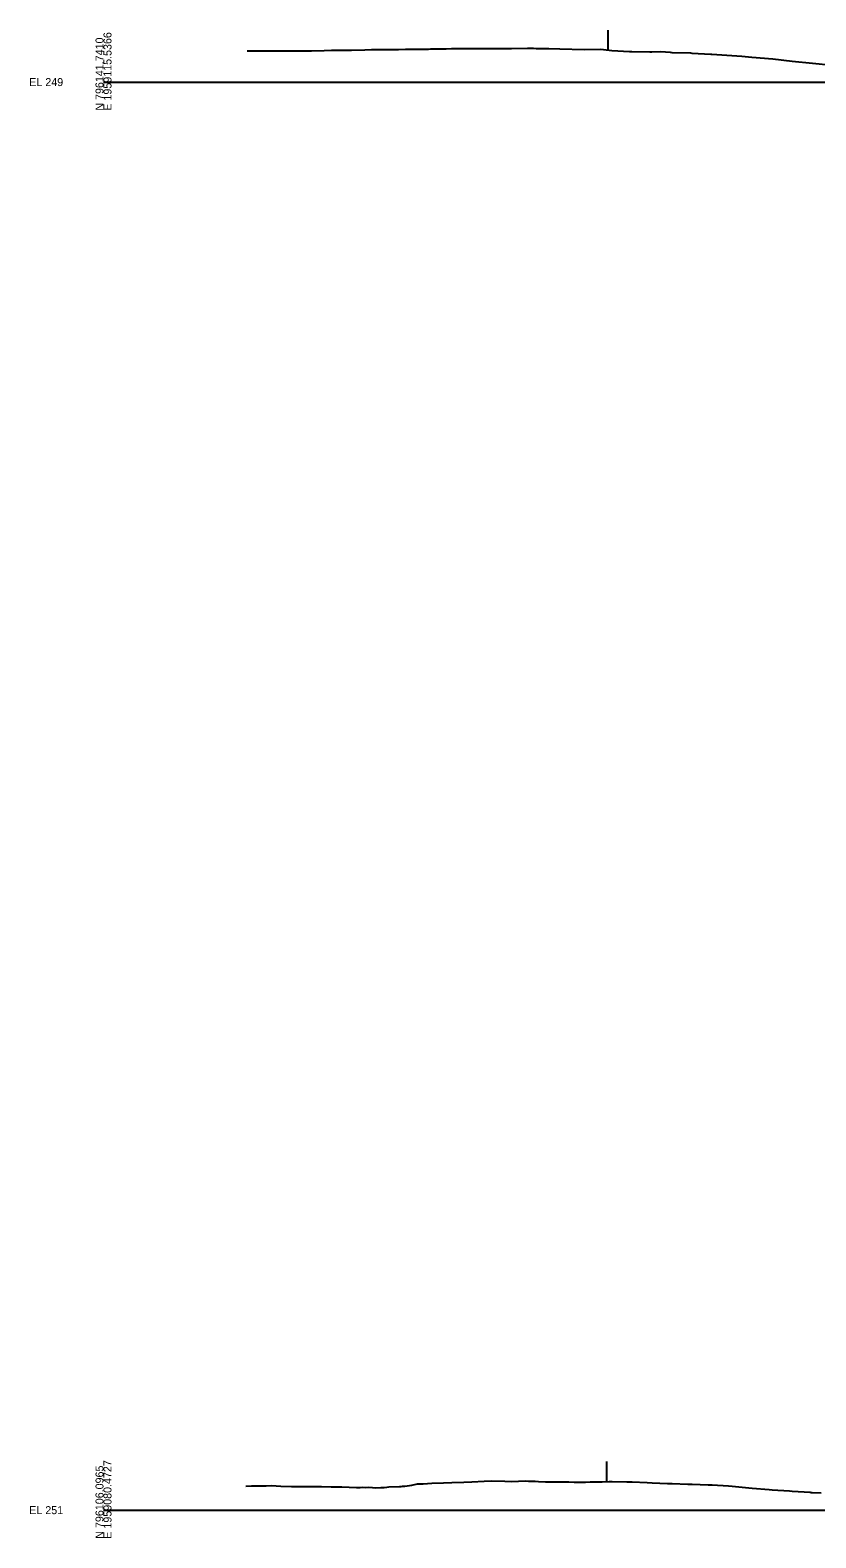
# Model space of a CAD drawing. Extents: x -4026 to 9638, y -10 to 19609.
# Drawn here: x -2026 to -1750, y 16490 to 17018 of the extents above; entities that cross this region are included whole.
import ezdxf

# ---------------------------------------------------------------- set-up
doc = ezdxf.new("R2010")
doc.units = 0
for name, color, linetype in [('Default', 7, 'Continuous'), ('RD_EX_Fence_Other', 7, 'Continuous'), ('RD_GPK_XS_Cell', 7, 'Continuous'), ('RD_XS_ExGround', 7, 'Continuous')]:
    doc.layers.add(name, color=color, linetype=linetype)

msp = doc.modelspace()

# ---------------------------------------------------------------- linework, layer by layer
at = {"layer": 'RD_EX_Fence_Other'}
for p, q in [((-1823.31, 17018.18), (-1823.31, 17011.18)), ((-1823.81, 16516.98), (-1823.81, 16509.98))]:
    msp.add_line(p, q, dxfattribs=at)
at = {"layer": 'RD_GPK_XS_Cell'}
for p, q in [((-2000, 17000), (-1650, 17000)), ((-2000, 16500), (-1650, 16500))]:
    msp.add_line(p, q, dxfattribs=at)
at = {"layer": 'RD_XS_ExGround'}
for points in [[(-1949.72, 17010.91), (-1948.22, 17010.93), (-1944.11, 17010.93), (-1941.21, 17010.93), (-1939.11, 17010.94), (-1936.98, 17010.95), (-1934.19, 17010.95), (-1929.86, 17010.97), (-1927.18, 17010.99), (-1922.73, 17011.06), (-1920.17, 17011.13), (-1917.9, 17011.18), (-1915.6, 17011.18), (-1913.15, 17011.22), (-1908.47, 17011.33), (-1906.14, 17011.36), (-1901.34, 17011.41), (-1899.34, 17011.43), (-1899.04, 17011.43), (-1898.6, 17011.44), (-1897.91, 17011.45), (-1896.67, 17011.46), (-1894.2, 17011.5), (-1893.04, 17011.51), (-1891.88, 17011.52), (-1890.6, 17011.52), (-1889.75, 17011.53), (-1887, 17011.58), (-1886.12, 17011.58), (-1885.45, 17011.59), (-1882.54, 17011.69), (-1879.95, 17011.67), (-1878.08, 17011.72), (-1872.82, 17011.78), (-1871.07, 17011.77), (-1865.69, 17011.75), (-1864.06, 17011.76), (-1858.56, 17011.77), (-1857.04, 17011.79), (-1851.43, 17011.86), (-1849.73, 17011.83), (-1849.35, 17011.83), (-1848.5, 17011.81), (-1845.48, 17011.77), (-1844.04, 17011.74), (-1840.11, 17011.67), (-1831.61, 17011.43), (-1825.97, 17011.52), (-1822.91, 17011.13), (-1821.97, 17011.04), (-1815.78, 17010.67), (-1814.96, 17010.66), (-1808.65, 17010.58), (-1807.95, 17010.58), (-1804.76, 17010.69), (-1801.52, 17010.42), (-1800.93, 17010.4), (-1794.39, 17010.2), (-1793.92, 17010.17), (-1787.26, 17009.78), (-1786.9, 17009.75), (-1779.89, 17009.29), (-1776.47, 17009.08), (-1772.88, 17008.73), (-1765.56, 17008.1), (-1758.74, 17007.28), (-1751.61, 17006.67), (-1744.82, 17005.9)], [(-1950.13, 16508.41), (-1948.13, 16508.48), (-1946.59, 16508.5), (-1945.03, 16508.53), (-1943.06, 16508.57), (-1941.12, 16508.58), (-1939.52, 16508.52), (-1937.9, 16508.45), (-1934.1, 16508.25), (-1930.77, 16508.24), (-1927.09, 16508.25), (-1923.64, 16508.24), (-1920.31, 16508.21), (-1916.56, 16508.12), (-1911.41, 16507.97), (-1910.78, 16507.97), (-1910.07, 16507.98), (-1909.26, 16508), (-1908.32, 16507.99), (-1907.23, 16508), (-1905.73, 16507.96), (-1904.63, 16507.87), (-1902.88, 16507.91), (-1901.72, 16507.99), (-1900.78, 16508.04), (-1900, 16508.12), (-1896.36, 16508.29), (-1895.76, 16508.33), (-1895.32, 16508.36), (-1894.44, 16508.42), (-1892.02, 16508.76), (-1890.02, 16509.18), (-1887.99, 16509.24), (-1885.01, 16509.42), (-1880.87, 16509.58), (-1877.99, 16509.71), (-1873.74, 16509.83), (-1870.98, 16509.97), (-1866.61, 16510.12), (-1863.97, 16510.25), (-1859.48, 16510.1), (-1856.95, 16510.07), (-1852.35, 16510.23), (-1851.13, 16510.18), (-1848.77, 16510.13), (-1847.62, 16510.08), (-1845.22, 16509.97), (-1841.64, 16509.95), (-1840.04, 16509.93), (-1839.26, 16509.92), (-1836.99, 16509.88), (-1835.17, 16509.86), (-1834.43, 16509.86), (-1832.6, 16509.86), (-1831.48, 16509.86), (-1831.17, 16509.86), (-1829.54, 16509.89), (-1826.55, 16509.93), (-1825.39, 16509.95), (-1822.85, 16510), (-1821.88, 16510.02), (-1816.7, 16509.96), (-1814.87, 16509.95), (-1809.57, 16509.74), (-1807.86, 16509.61), (-1802.44, 16509.36), (-1800.84, 16509.32), (-1795.31, 16509.14), (-1793.83, 16509.08), (-1788.18, 16508.89), (-1787.49, 16508.85), (-1786.82, 16508.81), (-1781.05, 16508.47), (-1779.8, 16508.39), (-1773.92, 16507.84), (-1772.79, 16507.72), (-1766.79, 16507.22), (-1765.77, 16507.17), (-1759.66, 16506.74), (-1758.76, 16506.68), (-1752.53, 16506.28), (-1752.13, 16506.24), (-1751.75, 16506.22), (-1748.6, 16506.03)]]:
    msp.add_lwpolyline(points, dxfattribs=at)

# ---------------------------------------------------------------- texts
at = {"layer": 'Default'}
for p in [(-2000, 17000), (-2000, 16500)]:
    msp.add_text('-', height=0.0001, dxfattribs=at).set_placement(p)
at = {"layer": 'RD_GPK_XS_Cell'}
for s, p in [('N 796141.7410', (-2000, 16990)), ('E 1959115.5366', (-1997.2, 16990)), ('E 1959080.4727', (-1997.2, 16490)), ('N 796106.0965', (-2000, 16490))]:
    msp.add_text(s, height=2.8, rotation=90, dxfattribs=at).set_placement(p)
for s, p in [('EL 249', (-2026, 16998.6)), ('EL 251', (-2026, 16498.6))]:
    msp.add_text(s, height=2.8, dxfattribs=at).set_placement(p)

doc.saveas('drawing.dxf')
